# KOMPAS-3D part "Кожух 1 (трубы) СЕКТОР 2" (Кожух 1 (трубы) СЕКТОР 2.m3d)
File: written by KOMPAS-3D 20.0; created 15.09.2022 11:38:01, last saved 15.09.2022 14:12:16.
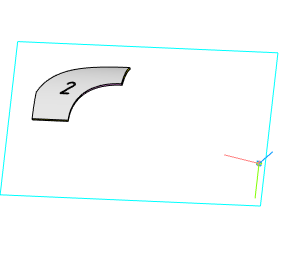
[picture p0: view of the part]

Document properties: Полное имя файла: D:\YAKOVLEV\ПРОЕКТЫ\ДЦ-2. ДП-7 Газопровод Окожушивание\ПРОБА Соединение труб. Окожушивание\Кожух 1 (трубы) СЕКТОР 2.m3d

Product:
- Part/product: Кожух 1 (трубы) СЕКТОР 2
    Материал: Сталь 45  ГОСТ 1050-2013 (density 7810 kg/m3)
    Масса: 92.2939

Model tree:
1. Эскиз:1  (with: Обечайка:1)  (labels: Кожух 1 (трубы))
2. Обечайка:1  (labels: Кожух 1 (трубы))
     Расстояние 1 = -2450; Смещение 1 = -50; Толщина листового тела = 20
3. Сгиб(1) - Обечайка:1
     Радиус сгиба = 980; Коэффициент = 0.4; Величина сгиба = 10; Зазор = 1
4. Касательная плоскость:1  (with: Обечайка:1)
5. Эскиз:2  (with: Обечайка:1)  (labels: Кожух 1 (трубы))
6. Вырез в листовом теле:2
     Глубина выреза = 2400
7. Разогнуть:1  (with: Обечайка:1)
8. Эскиз:3  (with: Обечайка:1, Вырез в листовом теле:2)
9. Вырез в листовом теле:3
     Глубина выреза = 1000
10. Эскиз:4  (with: Обечайка:1, Вырез в листовом теле:2, Вырез в листовом теле:3)
11. Вырез в листовом теле:4
     Глубина выреза = 1000
12. Эскиз:5  (with: Обечайка:1, Вырез в листовом теле:3, Вырез в листовом теле:4)
13. Вырез в листовом теле:5
     Глубина выреза = 10
14. Фаска:1  (with: Вырез в листовом теле:2, Вырез в листовом теле:3, Вырез в листовом теле:4)
     Угол = 45; Длина 1 = 3; Длина 2 = 3
15. Эскиз:6  (with: Вырез в листовом теле:5)
16. Вырез в листовом теле:6
     Глубина выреза = 1000
17. Эскиз:7  (with: Обечайка:1)
18. Вырез в листовом теле:7
     Глубина выреза = 0.1
19. Фаска:2  (with: Вырез в листовом теле:6)
     Угол = 20; Длина 1 = 18; Длина 2 = 6.55146
20. Согнуть:1  (with: Обечайка:1)
21. Развертка  (labels: Сталь 45  ГОСТ 1050-2013)

Expressions: v140*2
Referenced files in D:\YAKOVLEV\ПРОЕКТЫ\ДЦ-2. ДП-7 Газопровод Окожушивание\ПРОБА Соединение труб. Окожушивание\: Соединение труб. Окожушивание -2.a3d
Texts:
  Соединение труб. Окожушивание\Труба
